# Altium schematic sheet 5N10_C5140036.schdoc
size 127 x 101 mm
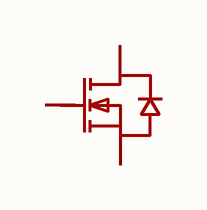
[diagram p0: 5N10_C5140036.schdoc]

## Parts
Q?  5n10-ms  [SOT-23-3_L2.9-W1.3-P1.90-LS2.4-BL-1]  (value not drawn)

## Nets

Not connected (* = marked no-connect by the designer): Q? 1(G) 2(S) 3(D)

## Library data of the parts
Q? = 5n10-ms: 数量:1个N沟道;漏源电压(Vdss):100V;连续漏极电流(Id):5A;导通电阻(RDS(on)):90mΩ@10V;耗散功率(Pd):2.5W;阈值电压(Vgs(th)):1.5V;; Manufacturer: MSKSEMI(美森科); Symbol: 5N10_C5140036; AddInBom: yes; ModelId: 115ef394a879442d90491e6127930138; ModelName: SOT-23-3_L2.9-W1.3-P1.90-LS2.4; ModelTransform: 114.173,94.488,0,0,0,0,0,0,0; Number: 1个N沟道; Drain to Source Voltage: 100V; Current - Continuous Drain(Id): 5A; Pd - Power Dissipation: 2.5W; Gate Threshold Voltage (Vgs(th)): 1.5V; Gate Charge(Qg): 18nC@10V; Input Capacitance(Ciss): 765pF; Reverse Transfer Capacitance (Crss@Vds): 33pF; Type: N沟道; Output Capacitance(Coss): 38pF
